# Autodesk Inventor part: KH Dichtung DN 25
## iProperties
Shininess: 64.0
Length Units: 11269
Angle Units: 11279
Time Units: 11290
Mass Units: 11283
Length Display Precision: 3
Angle Display Precision: 2
Compacted: True
Part Number: KH Dichtung DN 25
Document SubType Name: Modeling
Created: 2004-09
Material: Kst - PTFE(weiß)
Designer: AG
Manufacturer: Standard
Standards Organization: Custom
Density: 0.0
Volumn: 0.0
Area: 0.0
PropertySet Name: Model Information
Control State: 0
Master: False
Checked Out: False
Author: AG
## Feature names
1. Extrusion1
2. Bohrung1 [Hole]
3. Drehung1 [Revolution]
